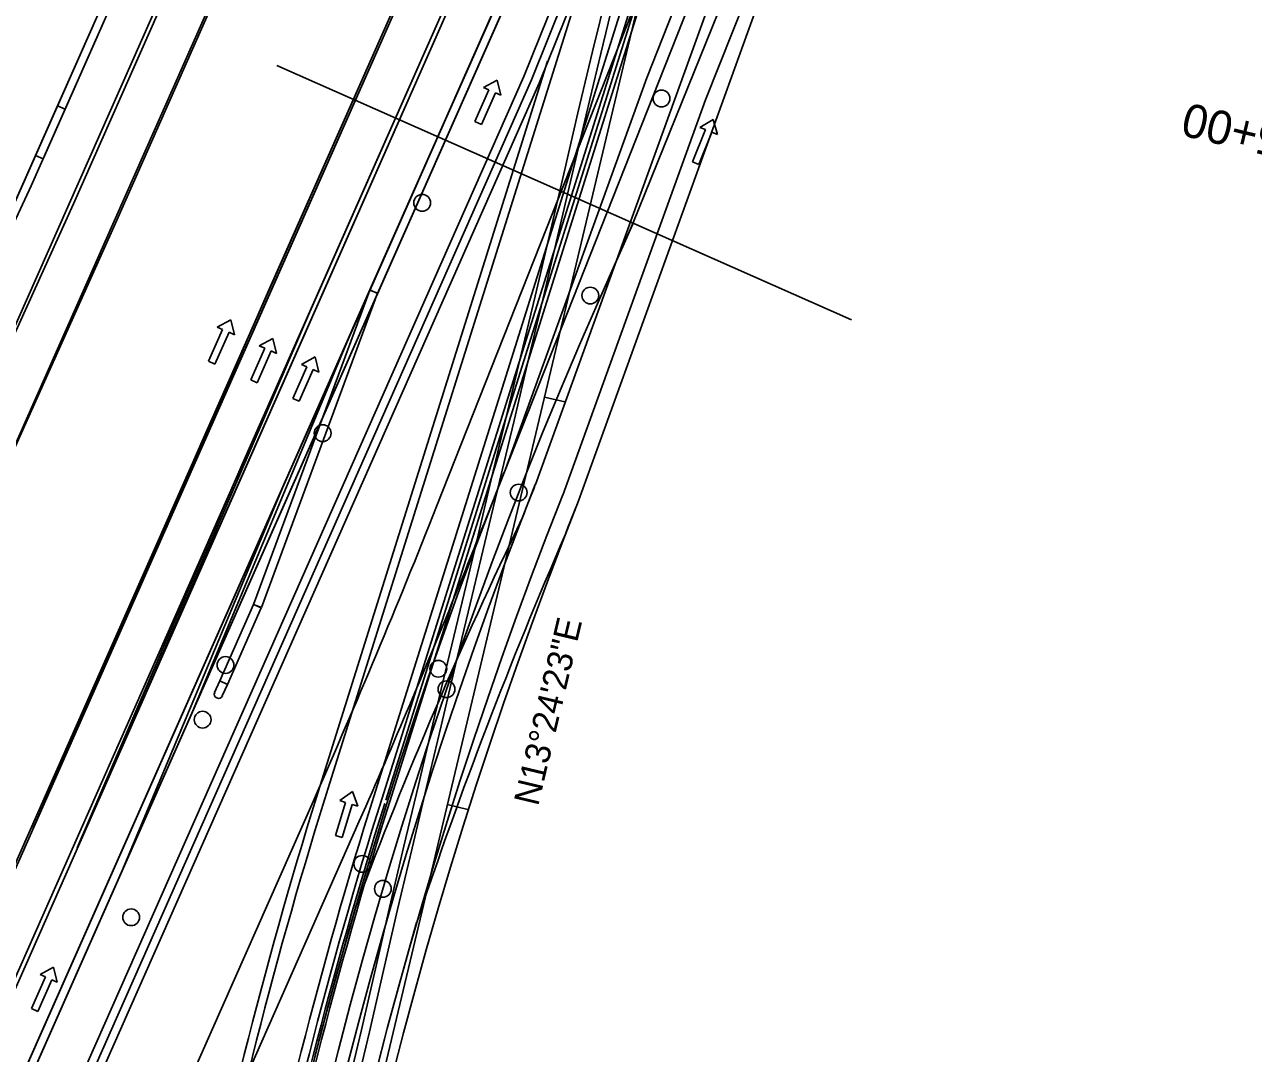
# Model space of a CAD drawing. Extents: x 659657 to 668193, y 633084 to 648639.
# Drawn here: x 662474.2 to 662767.5, y 643133.4 to 643378.9 of the extents above; entities that cross this region are included whole.
import ezdxf

# ---------------------------------------------------------------- set-up
doc = ezdxf.new("R2010")
doc.units = 0
for name, color, linetype in [('R_Border Prem', 7, 'Continuous'), ('R_MOT_Stage 1A', 7, 'Continuous'), ('R_MOT_Stage 1A_Striping', 7, 'Continuous'), ('R_MOT_Stage 1B', 7, 'Continuous'), ('R_MOT_Stage 1B_Striping', 7, 'Continuous'), ('R_MOT_Stage 1C', 7, 'Continuous'), ('R_MOT_Stage 1C_Striping', 7, 'Continuous'), ('R_MOT_Stage 2', 7, 'Continuous'), ('R_MOT_Stage 2_Striping', 7, 'Continuous'), ('R_MOT_Stage 3', 7, 'Continuous'), ('R_MOT_Stage 3_Striping', 7, 'Continuous'), ('R_MOT_Stage 3_Striping_PPM', 7, 'Continuous'), ('R_MOT_Stage 4', 7, 'Continuous'), ('R_MOT_Stage 4_Striping', 7, 'Continuous'), ('R_MOT_Stage 4_Striping_PPM', 7, 'Continuous'), ('R_MOT_Stage 5_Striping_PPM', 7, 'Continuous'), ('T_SIGNAL CONTROL CABINET', 7, 'Continuous')]:
    doc.layers.add(name, color=color, linetype=linetype)

msp = doc.modelspace()

# ---------------------------------------------------------------- linework, layer by layer
at = {"layer": 'R_Border Prem'}
msp.add_line((661686.79, 641562.92), (662861.91, 644217.67), dxfattribs=at)
at = {"layer": 'R_MOT_Stage 1A'}
for p, q in [((662556.65, 643315.57), (662645.7, 643516.74)), ((662558.48, 643314.76), (662647.53, 643515.93)), ((662528.88, 643240.48), (662556.62, 643315.51)), ((662556.62, 643315.51), (662558.5, 643314.82)), ((662556.65, 643315.57), (662558.48, 643314.76)), ((662530.75, 643239.78), (662558.5, 643314.82)), ((662528.9, 643240.53), (662520.81, 643222.25)), ((662530.73, 643239.72), (662522.64, 643221.44)), ((662528.88, 643240.48), (662530.75, 643239.78)), ((662528.9, 643240.53), (662530.73, 643239.72)), ((662520.81, 643222.25), (662519.59, 643219.5)), ((662520.81, 643222.25), (662522.64, 643221.44)), ((662521.42, 643218.69), (662522.64, 643221.44))]:
    msp.add_line(p, q, dxfattribs=at)
for points in [[(662551.12, 643124.33), (662554.61, 643138.95), (662557.97, 643153.57), (662561.32, 643168.19), (662564.78, 643182.79), (662568.25, 643197.38), (662571.71, 643211.98), (662575.16, 643226.55), (662578.66, 643241.13), (662582.15, 643255.72), (662585.63, 643270.31), (662589.1, 643284.9), (662592.58, 643299.49), (662596.06, 643314.08), (662599.49, 643328.68), (662602.91, 643343.25), (662606.32, 643357.86), (662609.82, 643372.44), (662613.33, 643387.02)], [(662553.06, 643123.87), (662556.56, 643138.49), (662559.92, 643153.12), (662563.27, 643167.74), (662566.73, 643182.33), (662570.19, 643196.92), (662573.65, 643211.52), (662577.11, 643226.08), (662580.6, 643240.67), (662584.09, 643255.26), (662587.57, 643269.85), (662591.05, 643284.44), (662594.53, 643299.03), (662598, 643313.62), (662601.43, 643328.23), (662604.85, 643342.8), (662608.27, 643357.4), (662611.76, 643371.97), (662615.27, 643386.56)]]:
    msp.add_lwpolyline(points, dxfattribs=at)
msp.add_arc((662520.51, 643219.1), 1, 156.1234, 336.1234, dxfattribs=at)
at = {"layer": 'R_MOT_Stage 1A_Striping'}
for p, q in [((662516.29, 643278.75), (662653.91, 643589.66)), ((662526.35, 643274.3), (662663.97, 643585.2)), ((662556.65, 643315.57), (662645.7, 643516.74)), ((662545.19, 643067.11), (662632.25, 643432.4)), ((662476.27, 643187.11), (662516.29, 643278.75)), ((662486.79, 643182.45), (662526.35, 643274.3))]:
    msp.add_line(p, q, dxfattribs=at)
for points in [[(662553.06, 643123.87), (662556.56, 643138.49), (662559.92, 643153.12), (662563.27, 643167.74), (662566.73, 643182.33), (662570.19, 643196.92), (662573.65, 643211.52), (662577.11, 643226.08), (662580.6, 643240.67), (662584.09, 643255.26), (662587.57, 643269.85), (662591.05, 643284.44), (662594.53, 643299.03), (662598, 643313.62), (662601.43, 643328.23), (662604.85, 643342.8), (662608.27, 643357.4), (662611.76, 643371.97), (662615.27, 643386.56)], [(662556.65, 643315.57), (662536.41, 643269.85), (662497.76, 643177.6)], [(662603.18, 643288.85), (662598.31, 643290.01)], [(662579.99, 643191.57), (662575.13, 643192.73)]]:
    msp.add_lwpolyline(points, dxfattribs=at)
at = {"layer": 'R_MOT_Stage 1B'}
for p, q in [((662641.39, 643454.72), (662559.48, 643194.07)), ((662643.3, 643454.12), (662561.39, 643193.47)), ((662599.08, 643370.13), (662545.17, 643198.57))]:
    msp.add_line(p, q, dxfattribs=at)
for centre in [(662569.13, 643336.35), (662545.37, 643281.39), (662522.18, 643226.05), (662516.72, 643213.01), (662499.67, 643165.85)]:
    msp.add_circle(centre, 2, dxfattribs=at)
for radius, start, end in [(1169.92, 162.55479, 175.09387), (1154.92, 162.55478, 175.08437), (1154.92, 162.55478, 175.08437), (1152.92, 162.55478, 175.08289), (1152.92, 162.55478, 175.08289)]:
    msp.add_arc((663661.27, 642847.83), radius, start, end, dxfattribs=at)
at = {"layer": 'R_MOT_Stage 1B_Striping'}
for p, q in [((662532.48, 643315.33), (662653.91, 643589.66)), ((662542.54, 643310.88), (662663.97, 643585.2)), ((662552.6, 643306.42), (662639.23, 643502.14)), ((662628.99, 643458.62), (662547.08, 643197.97)), ((662636.91, 643447.13), (662557.57, 643194.67)), ((662545.19, 643067.11), (662632.25, 643432.4)), ((662532.48, 643315.33), (662532.48, 643315.33)), ((662552.6, 643306.42), (662552.6, 643306.42))]:
    msp.add_line(p, q, dxfattribs=at)
for points in [[(662476.27, 643187.11), (662492.46, 643223.68), (662532.48, 643315.33)], [(662486.79, 643182.45), (662502.98, 643219.03), (662542.54, 643310.88)], [(662497.76, 643177.6), (662513.95, 643214.17), (662552.6, 643306.42)], [(662603.18, 643288.85), (662598.31, 643290.01)], [(662579.99, 643191.57), (662575.13, 643192.73)]]:
    msp.add_lwpolyline(points, dxfattribs=at)
for radius, end in [(1167.92, 175.09387), (1156.92, 175.08585)]:
    msp.add_arc((663661.27, 642847.83), radius, 162.55479, end, dxfattribs=at)
at = {"layer": 'R_MOT_Stage 1C'}
for centre in [(662626.26, 643361.25), (662609.26, 643314.23), (662592.17, 643267.21), (662574.93, 643220.28), (662559.75, 643172.65)]:
    msp.add_circle(centre, 2, dxfattribs=at)
at = {"layer": 'R_MOT_Stage 1C_Striping'}
for p, q in [((662492.46, 643223.68), (662694.85, 643680.89)), ((662502.98, 643219.03), (662705.36, 643676.24)), ((662513.95, 643214.17), (662716.34, 643671.38)), ((662596.14, 643269.11), (662675.65, 643489.09)), ((662606.43, 643265.22), (662685.93, 643485.2)), ((662492.46, 643223.68), (662476.27, 643187.11)), ((662502.98, 643219.03), (662486.79, 643182.45)), ((662513.95, 643214.17), (662497.76, 643177.6))]:
    msp.add_line(p, q, dxfattribs=at)
for radius, start in [(1145.42, 158.42034), (1134.42, 158.41207)]:
    msp.add_arc((663661.27, 642847.83), radius, start, 191.54523, dxfattribs=at)
at = {"layer": 'R_MOT_Stage 2'}
msp.add_lwpolyline([(662645.5, 643511.36), (661880.49, 641783.11), (661878.66, 641783.92), (662643.67, 643512.17)], close=True, dxfattribs=at)
for centre in [(662626.26, 643361.25), (662609.26, 643314.23), (662592.17, 643267.21), (662572.98, 643225.17), (662554.82, 643178.59)]:
    msp.add_circle(centre, 2, dxfattribs=at)
at = {"layer": 'R_MOT_Stage 2_Striping'}
for p, q in [((662653.91, 643589.66), (661803.9, 641669.37)), ((661813.96, 641664.92), (662663.97, 643585.2)), ((662596.14, 643269.11), (662675.65, 643489.09)), ((662606.43, 643265.22), (662685.93, 643485.2))]:
    msp.add_line(p, q, dxfattribs=at)
msp.add_lwpolyline([(661878.66, 641783.92), (662674.03, 643580.75)], dxfattribs=at)
for centre, radius, start, end in [((663661.27, 642847.83), 1145.42, 158.42034, 158.84387), ((663661.27, 642847.83), 1134.42, 158.41207, 158.84387), ((663631.94, 642760.95), 1153.06, 154.2867, 159.2867), ((663646.61, 642804.39), 1137.34, 156.53559, 161.53559), ((663661.27, 642847.83), 1153.42, 163.84387, 191.54523), ((663661.27, 642847.83), 1138.42, 163.84387, 191.54523)]:
    msp.add_arc(centre, radius, start, end, dxfattribs=at)
at = {"layer": 'R_MOT_Stage 3'}
for p, q in [((662595.25, 643365.71), (662706.63, 643644.52)), ((662597.09, 643364.94), (662708.49, 643643.78)), ((662227.19, 642534.22), (662595.25, 643365.71)), ((662229.06, 642533.51), (662597.09, 643364.94))]:
    msp.add_line(p, q, dxfattribs=at)
at = {"layer": 'R_MOT_Stage 3_Striping'}
for p, q in [((662792.14, 643794.42), (662622.73, 643366.22)), ((662593.4, 643366.49), (662704.78, 643645.27)), ((662215.01, 642538.82), (662583.35, 643370.94)), ((662225.31, 642534.93), (662593.4, 643366.49)), ((662588.66, 643271.94), (662622.73, 643366.22))]:
    msp.add_line(p, q, dxfattribs=at)
at = {"layer": 'R_MOT_Stage 3_Striping_PPM'}
for p, q in [((661859, 641792.62), (662694.85, 643680.89)), ((661869.52, 641787.96), (662705.36, 643676.24)), ((662685.93, 643485.2), (662636.76, 643360.91)), ((662602.69, 643266.63), (662636.76, 643360.91))]:
    msp.add_line(p, q, dxfattribs=at)
for radius, start in [(1153.42, 158.42628), (1138.42, 158.41509)]:
    msp.add_arc((663661.27, 642847.83), radius, start, 191.54523, dxfattribs=at)
at = {"layer": 'R_MOT_Stage 4'}
for p, q in [((662482.06, 643359.52), (662648.01, 643734.43)), ((662483.88, 643358.71), (662649.84, 643733.63)), ((662482.06, 643359.52), (662483.88, 643358.71))]:
    msp.add_line(p, q, dxfattribs=at)
msp.add_lwpolyline([(662478.62, 643346.83), (662476.79, 643347.64), (662482.06, 643359.52), (662483.88, 643358.71)], close=True, dxfattribs=at)
at = {"layer": 'R_MOT_Stage 4_Striping'}
for p, q in [((662792.14, 643794.42), (662622.73, 643366.22)), ((662475.79, 643340.42), (662672.54, 643784.91)), ((662593.4, 643366.49), (662704.78, 643645.27)), ((662215.01, 642538.82), (662583.35, 643370.94)), ((662225.31, 642534.93), (662593.4, 643366.49)), ((662588.66, 643271.94), (662622.73, 643366.22)), ((662475.79, 643340.42), (662433.48, 643249.79)), ((662485.93, 643336.15), (662444.46, 643244.94)), ((662495.91, 643331.52), (662454.97, 643240.28))]:
    msp.add_line(p, q, dxfattribs=at)
for points in [[(662485.93, 643336.15), (662688.23, 643793.18), (662727.79, 643885.03)], [(662495.91, 643331.52), (662698.29, 643788.73), (662738.31, 643880.37)]]:
    msp.add_lwpolyline(points, dxfattribs=at)
at = {"layer": 'R_MOT_Stage 4_Striping_PPM'}
for p, q in [((661859, 641792.62), (662694.85, 643680.89)), ((661869.52, 641787.96), (662705.36, 643676.24)), ((662685.93, 643485.2), (662636.76, 643360.91)), ((662602.69, 643266.63), (662636.76, 643360.91))]:
    msp.add_line(p, q, dxfattribs=at)
for radius, start in [(1153.42, 158.42628), (1138.42, 158.41509)]:
    msp.add_arc((663661.27, 642847.83), radius, start, 191.54523, dxfattribs=at)
at = {"layer": 'R_MOT_Stage 5_Striping_PPM'}
for p, q in [((662572.57, 643263.89), (662866.47, 644006.76)), ((662572.57, 643263.89), (662866.47, 644006.76)), ((662572.57, 643263.89), (662866.47, 644006.76)), ((662444.46, 643244.94), (662727.79, 643885.03)), ((662454.97, 643240.28), (662738.31, 643880.37)), ((661859, 641792.62), (662694.85, 643680.89)), ((661869.52, 641787.96), (662705.36, 643676.24)), ((662215.01, 642538.82), (662716.34, 643671.38)), ((662685.93, 643485.2), (662636.76, 643360.91)), ((662433.48, 643249.79), (662518.92, 643442.81)), ((662602.69, 643266.63), (662636.76, 643360.91)), ((662588.74, 643272.15), (662583.73, 643259.47)), ((662125.58, 642250.33), (662543.15, 643193.66)), ((662435.5, 642920.82), (662554.12, 643188.8))]:
    msp.add_line(p, q, dxfattribs=at)
msp.add_lwpolyline([(662588.74, 643272.15), (662625.61, 643365.32), (662736.19, 643644.85)], dxfattribs=at)
for centre, radius, start, end in [((663661.27, 642847.83), 1153.42, 158.42628, 191.54523), ((663661.27, 642847.83), 1138.42, 158.41509, 191.54523), ((660802.22, 643964.28), 1903.86, 336.12343, 338.41509), ((660802.22, 643964.28), 1915.86, 337.02865, 338.41509), ((660802.22, 643964.28), 1915.86, 336.12343, 337.02865)]:
    msp.add_arc(centre, radius, start, end, dxfattribs=at)
at = {"layer": 'T_SIGNAL CONTROL CABINET'}
for p, q in [((662619.44, 643331.41), (662810.32, 643804.65)), ((662619.45, 643331.46), (662810.32, 643804.65)), ((662642.34, 643454.42), (662560.43, 643193.77)), ((662534.43, 643369.15), (662671.6, 643308.43)), ((662583.77, 643363.86), (662587.01, 643365.62)), ((662587.01, 643365.62), (662587.88, 643362.04)), ((662585.05, 643363.29), (662581.7, 643355.73)), ((662586.6, 643362.61), (662583.25, 643355.04)), ((662583.77, 643363.86), (662585.05, 643363.29)), ((662586.6, 643362.61), (662587.88, 643362.04)), ((662635.43, 643354.36), (662638.61, 643356.23)), ((662638.61, 643356.23), (662639.6, 643352.67)), ((662581.7, 643355.73), (662583.25, 643355.04)), ((662636.74, 643353.83), (662633.64, 643346.16)), ((662638.3, 643353.2), (662635.2, 643345.53)), ((662635.43, 643354.36), (662636.74, 643353.83)), ((662638.3, 643353.2), (662639.6, 643352.67)), ((662633.64, 643346.16), (662635.2, 643345.53)), ((662611.14, 643312.67), (662619.47, 643331.5)), ((662611.14, 643312.67), (662619.45, 643331.46)), ((662520.19, 643306.71), (662523.43, 643308.47)), ((662520.19, 643306.71), (662521.48, 643306.14)), ((662523.43, 643308.47), (662524.31, 643304.89)), ((662521.48, 643306.14), (662518.13, 643298.57)), ((662523.02, 643305.46), (662519.67, 643297.89)), ((662523.02, 643305.46), (662524.31, 643304.89)), ((662530.25, 643302.26), (662533.49, 643304.02)), ((662533.49, 643304.02), (662534.37, 643300.44)), ((662531.54, 643301.69), (662528.19, 643294.12)), ((662533.08, 643301.01), (662529.73, 643293.44)), ((662530.25, 643302.26), (662531.54, 643301.69)), ((662533.08, 643301.01), (662534.37, 643300.44)), ((662518.13, 643298.57), (662519.67, 643297.89)), ((662540.31, 643297.81), (662543.55, 643299.57)), ((662540.31, 643297.81), (662541.6, 643297.24)), ((662543.55, 643299.57), (662544.43, 643295.98)), ((662541.6, 643297.24), (662538.25, 643289.67)), ((662543.14, 643296.55), (662539.79, 643288.99)), ((662543.14, 643296.55), (662544.43, 643295.98)), ((662528.19, 643294.12), (662529.73, 643293.44)), ((662538.25, 643289.67), (662539.79, 643288.99)), ((662549.48, 643193.69), (662552.48, 643195.83)), ((662552.48, 643195.83), (662553.79, 643192.39)), ((662550.83, 643193.28), (662548.44, 643185.36)), ((662549.48, 643193.69), (662550.83, 643193.28)), ((662552.45, 643192.79), (662550.05, 643184.87)), ((662552.45, 643192.79), (662553.79, 643192.39)), ((662548.44, 643185.36), (662550.05, 643184.87)), ((662477.91, 643152.2), (662481.15, 643153.96)), ((662477.91, 643152.2), (662481.15, 643153.96)), ((662481.15, 643153.96), (662482.02, 643150.38)), ((662481.15, 643153.96), (662482.02, 643150.38)), ((662479.2, 643151.63), (662475.85, 643144.07)), ((662479.2, 643151.63), (662475.85, 643144.07)), ((662480.74, 643150.95), (662477.39, 643143.38)), ((662480.74, 643150.95), (662477.39, 643143.38)), ((662477.91, 643152.2), (662479.2, 643151.63)), ((662477.91, 643152.2), (662479.2, 643151.63)), ((662480.74, 643150.95), (662482.02, 643150.38)), ((662480.74, 643150.95), (662482.02, 643150.38)), ((662475.85, 643144.07), (662477.39, 643143.38)), ((662475.85, 643144.07), (662477.39, 643143.38))]:
    msp.add_line(p, q, dxfattribs=at)
for radius, start, end in [(1148.42, 156.12343, 191.54523), (1153.92, 162.59387, 175.08363)]:
    msp.add_arc((663661.27, 642847.83), radius, start, end, dxfattribs=at)

# ---------------------------------------------------------------- texts
at = {"layer": 'R_MOT_Stage 1A_Striping'}
for s, height, rotation, p in [('P.C. STA. 185+46.38', 8, 166.5936, (662850.52, 643374.81)), ('185+00', 8, 166.5936, (662786.75, 643352.01)), ('N13%%d24\'23"E', 6, 76.5936, (662596.79, 643192.2))]:
    msp.add_text(s, height=height, rotation=rotation, dxfattribs=at).set_placement(p)
at = {"layer": 'R_MOT_Stage 1B_Striping'}
for s, height, rotation, p in [('P.C. STA. 185+46.38', 8, 166.5936, (662850.52, 643374.81)), ('185+00', 8, 166.5936, (662786.75, 643352.01)), ('N13%%d24\'23"E', 6, 76.5936, (662596.79, 643192.2))]:
    msp.add_text(s, height=height, rotation=rotation, dxfattribs=at).set_placement(p)

doc.saveas('drawing.dxf')
